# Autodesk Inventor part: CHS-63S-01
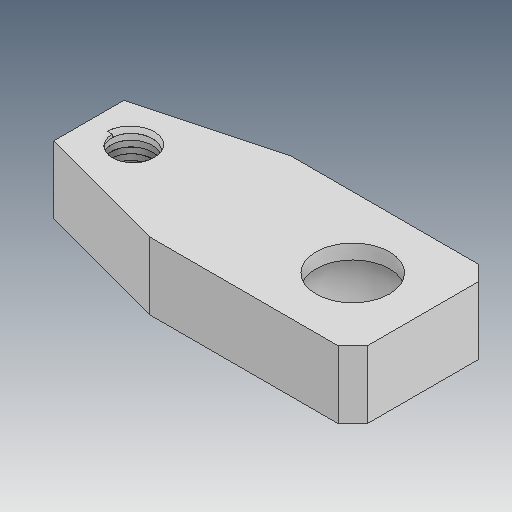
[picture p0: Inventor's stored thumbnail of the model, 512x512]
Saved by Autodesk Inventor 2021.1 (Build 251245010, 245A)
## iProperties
Created: 2019-05
Part Number: CHS-63S-01
Material: Ogólny
Document SubType Name: Modeling
Designer: user
Density: 1 g/cm^3
Appearance: Domyślna
Author: user
Revision Number: ÈÎºÎ
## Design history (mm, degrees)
feature "ÊäÈë1"
node "Bryła1"
